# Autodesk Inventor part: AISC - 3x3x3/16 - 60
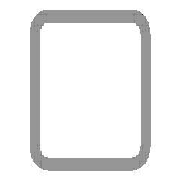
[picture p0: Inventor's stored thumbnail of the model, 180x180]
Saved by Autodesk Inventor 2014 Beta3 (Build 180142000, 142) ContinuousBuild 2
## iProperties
IsCustomPart: 1
Created: 2011-01
Part Number: AISC - 3x3x3/16 - 60
Material: Steel, Mild
Description: Tube
Document SubType Name: Modeling
Standard: ANSI
Designer: Beta-8540w
Standards Organization: ANSI
Language: en-US
Size Designation: 3x3x3/16
Categories: <MemberInstance><Categories><Category DisplayName="Structural Shapes" InternalName="089c4875-fa83-4c05-b084-43b9cc11f5ed" Mnemonic="GRDR"><CategoryParameter Dis
Stock Number: 3x3x3/16
Density: 7.86 g/cm^3
Appearance: Steel
G_L: 60.000 in
G_W: 3.000 in
G_H: 3.000 in
_CCFamilyMember: 9
_CCFamilyDisplayName: ANSI AISC (Square) - Tube
_FrameMemberDoc: Frame Member File
_Version: 15.0.0
_GetPNFromCC: 1
Author: Beta-8540w
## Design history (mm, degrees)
node "Start plane"
node "End plane"
sketch "Sketch"
  geometry: L1 (-38.1, -28.575)-(-38.1, 28.575); L2 (-28.575, 38.1)-(28.575, 38.1); L3 (38.1, 28.575)-(38.1, -28.575); L4 (28.575, -38.1)-(-28.575, -38.1); L5 (-28.575, 33.337)-(28.575, 33.338); L6 (33.338, 28.575)-(33.338, -28.575); L7 (28.575, -33.337)-(-28.575, -33.338); L8 (-33.338, -28.575)-(-33.338, 28.575); L9 (0, 56.102)-(0, -56.102) reference; L10 (-56.102, 0)-(56.102, 0) reference; A1 r 9.525 centre (-28.575, -28.575) between (-38.1, -28.575) and (-28.575, -38.1); A2 r 9.525 centre (-28.575, 28.575) between (-28.575, 38.1) and (-38.1, 28.575); A3 r 9.525 centre (28.575, 28.575) between (38.1, 28.575) and (28.575, 38.1); A4 r 9.525 centre (28.575, -28.575) between (28.575, -38.1) and (38.1, -28.575); A5 r 4.763 centre (-28.575, 28.575) between (-28.575, 33.337) and (-33.338, 28.575); A6 r 4.763 centre (28.575, 28.575) between (33.338, 28.575) and (28.575, 33.338); A7 r 4.763 centre (28.575, -28.575) between (28.575, -33.337) and (33.338, -28.575); A8 r 4.763 centre (-28.575, -28.575) between (-33.338, -28.575) and (-28.575, -33.338)
  constraints: 16 end point, 16 point on circle, 8 centre point, 8 tangent, 4 parallel, 3 equal radius, 2 perpendicular, 7 other
  dimensions: "d10" = 76.2 distance between parallel lines of L2 L4 (= G_H); "d11" = 76.2 distance between parallel lines of L1 L3 (= G_W); "d12" = 4.7625 distance between parallel lines of L3 L6 (= G_T); "d15" = 38.1 distance between parallel lines of L2 L10 (= 0.5 x d10); "d16" = 38.1 distance between parallel lines of L9 L3 (= 0.5 x d11); "d17" = 9.525 radius of A1 (= G_IR)
extrude "Body" new body sketch "Sketch" stored distance "d3" = 1524 (= G_L); taper "d4" = 0 deg
node "Driven Length"
  sketch "Sketch3"
    geometry: L1 (0, 0)-(10, 0) reference
    constraints: 2 end point, 1 horizontal
  workplane "Work Plane3"
  sketch "Sketch4"
    geometry: L1 (-2, 0)-(12, 0) reference; L2 (-2, 1524)-(12, 1524) reference
    dimensions: "d19" = 1524 distance between parallel lines of L1 L2 (derived)
body "Solid1"
other parameters: "G_W" = 76.2 [user parameter; used in 1 equation term], "G_H" = 76.2 [user parameter; used in 1 equation term], "G_T" = 4.7625 [user parameter; used in 1 equation term], "G_IR" = 9.525 [user parameter; used in 1 equation term], "G_L" = 1524 (= d19) [user parameter; used in 1 equation term], "G_OFFSET_START" = 0 [user parameter; used in 1 equation term], "G_OFFSET_END" = 0 [user parameter; used in 1 equation term], "d13" = 0 (computed from G_OFFSET_START), "d14" = 1524 (= G_OFFSET_END + B_L), "B_L" = 1524 [user parameter; used in 1 equation term], "d18" = 90 deg
